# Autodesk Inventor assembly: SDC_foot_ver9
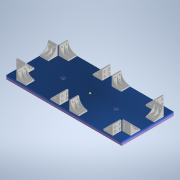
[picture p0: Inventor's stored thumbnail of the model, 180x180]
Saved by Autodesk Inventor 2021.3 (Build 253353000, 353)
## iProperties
Created: 2022-02
Part Number: SDC_foot_ver9
Document SubType Name: Assembly
Designer: kengo
Author: kengo
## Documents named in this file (6)
- C:\Users\kengo\Documents\S2S_frame\SDC345\frame_misumi_ver9\foot\SDC_foot_ver9.iam
- C:\Users\kengo\Documents\S2S_frame\SDC345\frame_misumi_ver9\foot\SDC_Anker_down_plate_ver9.ipt
- C:\Users\kengo\Documents\S2S_frame\SDC345\frame_misumi_ver9\foot\SDC_Anker_plate_ver9.ipt
- C:\Users\kengo\Documents\S2S_frame\SDC345\frame_misumi_ver9\foot\SDC_Anker_PVC_plate_ver9.ipt
- C:\Users\kengo\Documents\S2S_frame\SDC345\frame_misumi_ver9\HBLFSDW8-90-SET_foot.iam
- C:\Users\kengo\Documents\S2S_frame\SDC345\frame_misumi_ver9\foot\SJPNGB10-P17-B15-G8.ipt
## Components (16 placed, 5 different names)
1. SDC_Anker_down_plate_ver9:1 — メイト:1, フラッシュ:1, フラッシュ:2, メイト:2, フラッシュ:3, フラッシュ:4, フラッシュ:7, フラッシュ:11, フラッシュ:14, フラッシュ:22, 回転:1
2. SDC_Anker_plate_ver9:1 — メイト:1, フラッシュ:1, フラッシュ:2, メイト:3, フラッシュ:5, フラッシュ:6, メイト:4, フラッシュ:8, メイト:5, フラッシュ:9, メイト:7, フラッシュ:10, メイト:8, フラッシュ:12, フラッシュ:13, メイト:9, フラッシュ:15, メイト:10, フラッシュ:16, メイト:12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
3. SDC_Anker_PVC_plate_ver9:1 — メイト:2, フラッシュ:3, フラッシュ:4
4. HBLFSDW8-90-SET_foot:1 [sub-assembly] — メイト:4, フラッシュ:7, フラッシュ:8
5. HBLFSDW8-90-SET_foot:2 [sub-assembly] — メイト:5, フラッシュ:9, メイト:6
6. HBLFSDW8-90-SET_foot:3 [sub-assembly] — メイト:7, フラッシュ:10, フラッシュ:11, メイト:11
7. HBLFSDW8-90-SET_foot:4 [sub-assembly] — メイト:8, フラッシュ:12, フラッシュ:13
8. HBLFSDW8-90-SET_foot:5 [sub-assembly] — メイト:3, フラッシュ:5, フラッシュ:6, メイト:6
9. HBLFSDW8-90-SET_foot:6 [sub-assembly] — メイト:9, フラッシュ:14, フラッシュ:15
10. HBLFSDW8-90-SET_foot:7 [sub-assembly] — メイト:13, メイト:14, フラッシュ:19, メイト:16
11. HBLFSDW8-90-SET_foot:8 [sub-assembly] — メイト:15, フラッシュ:20, メイト:16
12. HBLFSDW8-90-SET_foot:9 [sub-assembly] — メイト:10, フラッシュ:16, メイト:11
13. HBLFSDW8-90-SET_foot:10 [sub-assembly] — メイト:12, フラッシュ:17, フラッシュ:18, メイト:14
14. HBLFSDW8-90-SET_foot:11 [sub-assembly] — メイト:17, フラッシュ:21, フラッシュ:22
15. HBLFSDW8-90-SET_foot:12 [sub-assembly] — メイト:18, フラッシュ:23, フラッシュ:24
16. SJPNGB10-P17-B15-G8:1 — 回転:1
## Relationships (43: Flush 24, Mate 18, RevoluteJoint 1)
- メイト:1 [Mate]: SDC_Anker_down_plate_ver9:1 ↔ SDC_Anker_plate_ver9:1
- フラッシュ:1 [Flush]: SDC_Anker_down_plate_ver9:1 ↔ SDC_Anker_plate_ver9:1
- フラッシュ:2 [Flush]: SDC_Anker_down_plate_ver9:1 ↔ SDC_Anker_plate_ver9:1
- メイト:2 [Mate]: SDC_Anker_down_plate_ver9:1 ↔ SDC_Anker_PVC_plate_ver9:1
- フラッシュ:3 [Flush]: SDC_Anker_down_plate_ver9:1 ↔ SDC_Anker_PVC_plate_ver9:1
- フラッシュ:4 [Flush]: SDC_Anker_down_plate_ver9:1 ↔ SDC_Anker_PVC_plate_ver9:1
- メイト:3 [Mate]: SDC_Anker_plate_ver9:1 ↔ HBLFSDW8-90-SET_foot:5
- フラッシュ:5 [Flush]: SDC_Anker_plate_ver9:1 ↔ HBLFSDW8-90-SET_foot:5
- フラッシュ:6 [Flush]: SDC_Anker_plate_ver9:1 ↔ HBLFSDW8-90-SET_foot:5
- メイト:4 [Mate]: SDC_Anker_plate_ver9:1 ↔ HBLFSDW8-90-SET_foot:1
- フラッシュ:7 [Flush]: SDC_Anker_down_plate_ver9:1 ↔ HBLFSDW8-90-SET_foot:1
- フラッシュ:8 [Flush]: SDC_Anker_plate_ver9:1 ↔ HBLFSDW8-90-SET_foot:1
- メイト:5 [Mate]: SDC_Anker_plate_ver9:1 ↔ HBLFSDW8-90-SET_foot:2
- フラッシュ:9 [Flush]: SDC_Anker_plate_ver9:1 ↔ HBLFSDW8-90-SET_foot:2
- メイト:6 [Mate]: HBLFSDW8-90-SET_foot:2 ↔ HBLFSDW8-90-SET_foot:5
- メイト:7 [Mate]: SDC_Anker_plate_ver9:1 ↔ HBLFSDW8-90-SET_foot:3
- フラッシュ:10 [Flush]: SDC_Anker_plate_ver9:1 ↔ HBLFSDW8-90-SET_foot:3
- フラッシュ:11 [Flush]: SDC_Anker_down_plate_ver9:1 ↔ HBLFSDW8-90-SET_foot:3
- メイト:8 [Mate]: SDC_Anker_plate_ver9:1 ↔ HBLFSDW8-90-SET_foot:4
- フラッシュ:12 [Flush]: SDC_Anker_plate_ver9:1 ↔ HBLFSDW8-90-SET_foot:4
- フラッシュ:13 [Flush]: SDC_Anker_plate_ver9:1 ↔ HBLFSDW8-90-SET_foot:4
- メイト:9 [Mate]: SDC_Anker_plate_ver9:1 ↔ HBLFSDW8-90-SET_foot:6
- フラッシュ:14 [Flush]: SDC_Anker_down_plate_ver9:1 ↔ HBLFSDW8-90-SET_foot:6
- フラッシュ:15 [Flush]: SDC_Anker_plate_ver9:1 ↔ HBLFSDW8-90-SET_foot:6
- メイト:10 [Mate]: SDC_Anker_plate_ver9:1 ↔ HBLFSDW8-90-SET_foot:9
- フラッシュ:16 [Flush]: SDC_Anker_plate_ver9:1 ↔ HBLFSDW8-90-SET_foot:9
- メイト:11 [Mate]: HBLFSDW8-90-SET_foot:3 ↔ HBLFSDW8-90-SET_foot:9
- メイト:12 [Mate]: SDC_Anker_plate_ver9:1 ↔ HBLFSDW8-90-SET_foot:10
- フラッシュ:17 [Flush]: SDC_Anker_plate_ver9:1 ↔ HBLFSDW8-90-SET_foot:10
- フラッシュ:18 [Flush]: SDC_Anker_plate_ver9:1 ↔ HBLFSDW8-90-SET_foot:10
- メイト:13 [Mate]: SDC_Anker_plate_ver9:1 ↔ HBLFSDW8-90-SET_foot:7
- メイト:14 [Mate]: HBLFSDW8-90-SET_foot:7 ↔ HBLFSDW8-90-SET_foot:10
- フラッシュ:19 [Flush]: SDC_Anker_plate_ver9:1 ↔ HBLFSDW8-90-SET_foot:7
- メイト:15 [Mate]: SDC_Anker_plate_ver9:1 ↔ HBLFSDW8-90-SET_foot:8
- フラッシュ:20 [Flush]: SDC_Anker_plate_ver9:1 ↔ HBLFSDW8-90-SET_foot:8
- メイト:16 [Mate]: HBLFSDW8-90-SET_foot:7 ↔ HBLFSDW8-90-SET_foot:8
- メイト:17 [Mate]: SDC_Anker_plate_ver9:1 ↔ HBLFSDW8-90-SET_foot:11
- フラッシュ:21 [Flush]: SDC_Anker_plate_ver9:1 ↔ HBLFSDW8-90-SET_foot:11
- フラッシュ:22 [Flush]: SDC_Anker_down_plate_ver9:1 ↔ HBLFSDW8-90-SET_foot:11
- メイト:18 [Mate]: SDC_Anker_plate_ver9:1 ↔ HBLFSDW8-90-SET_foot:12
- フラッシュ:23 [Flush]: SDC_Anker_plate_ver9:1 ↔ HBLFSDW8-90-SET_foot:12
- フラッシュ:24 [Flush]: SDC_Anker_plate_ver9:1 ↔ HBLFSDW8-90-SET_foot:12
- 回転:1 [RevoluteJoint]: SDC_Anker_down_plate_ver9:1 ↔ SJPNGB10-P17-B15-G8:1
